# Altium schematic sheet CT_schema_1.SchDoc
size 532 x 258 mm
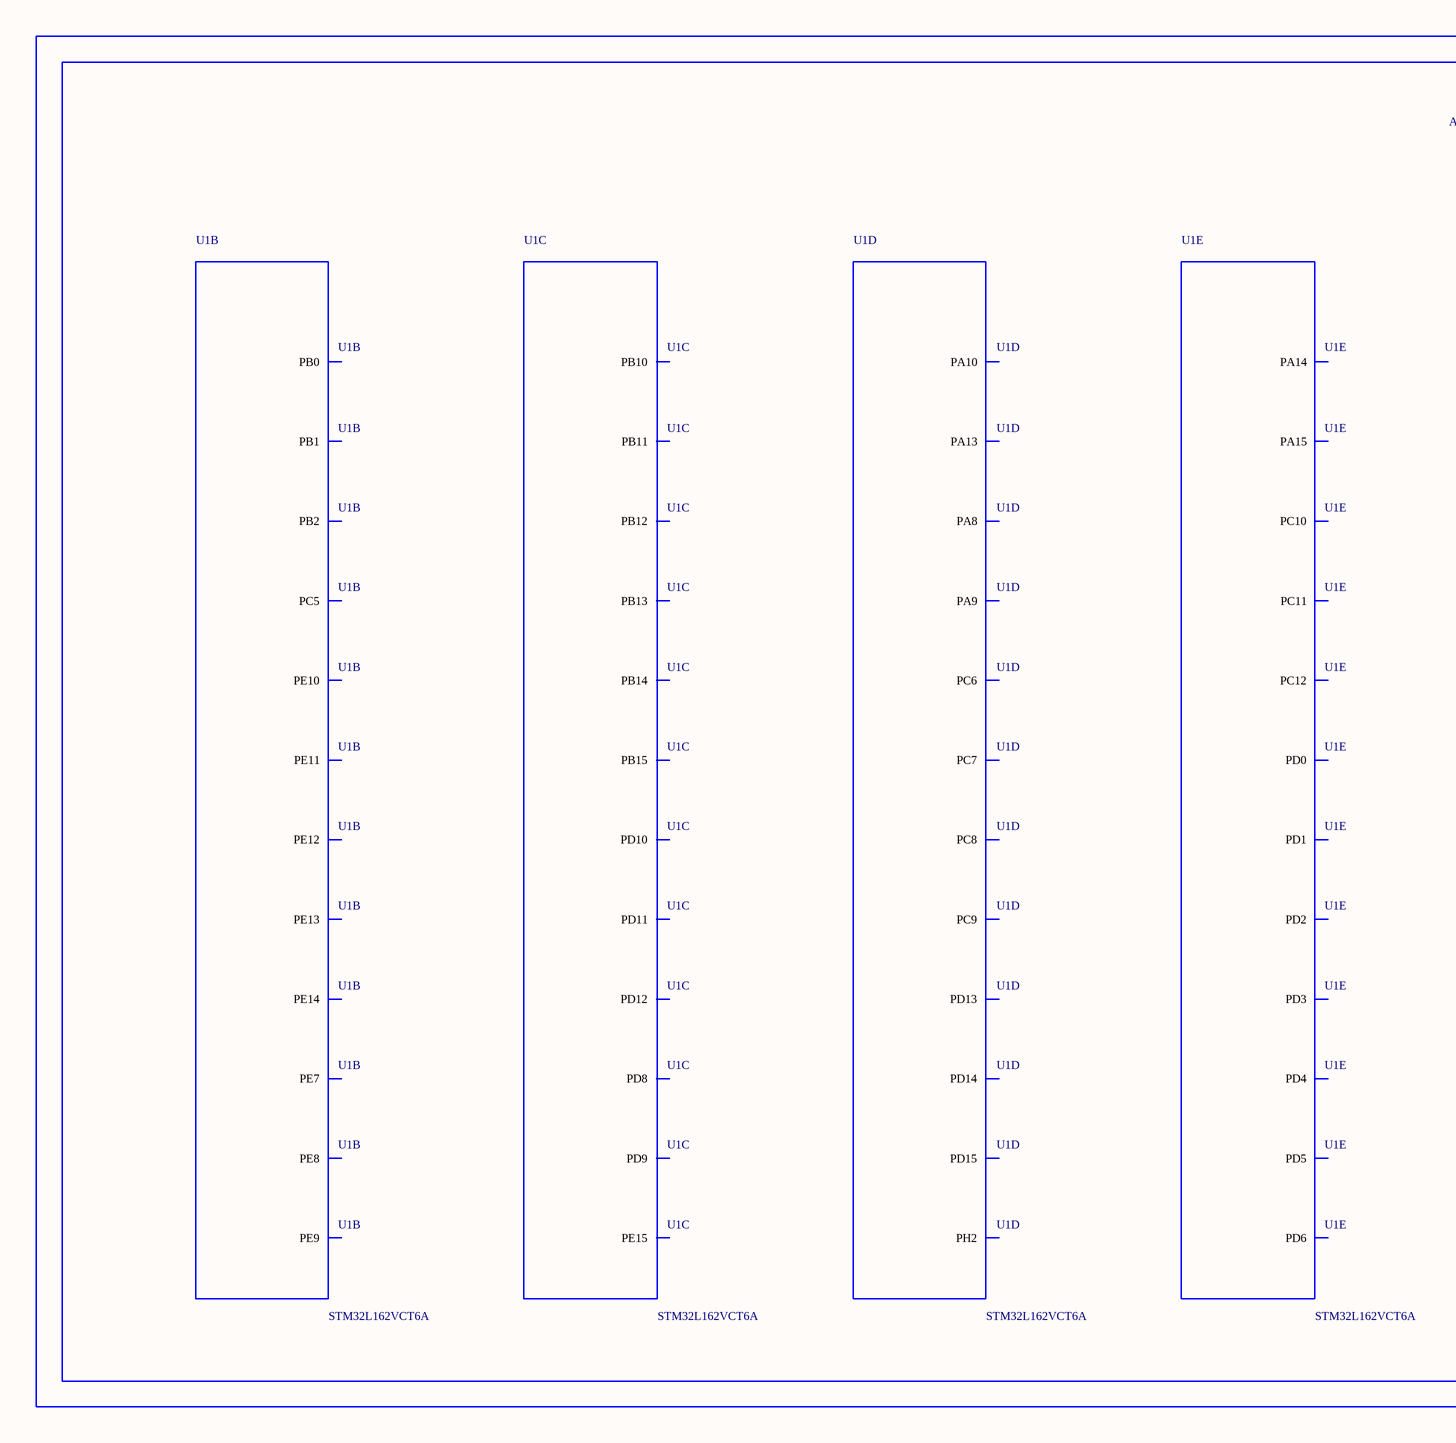
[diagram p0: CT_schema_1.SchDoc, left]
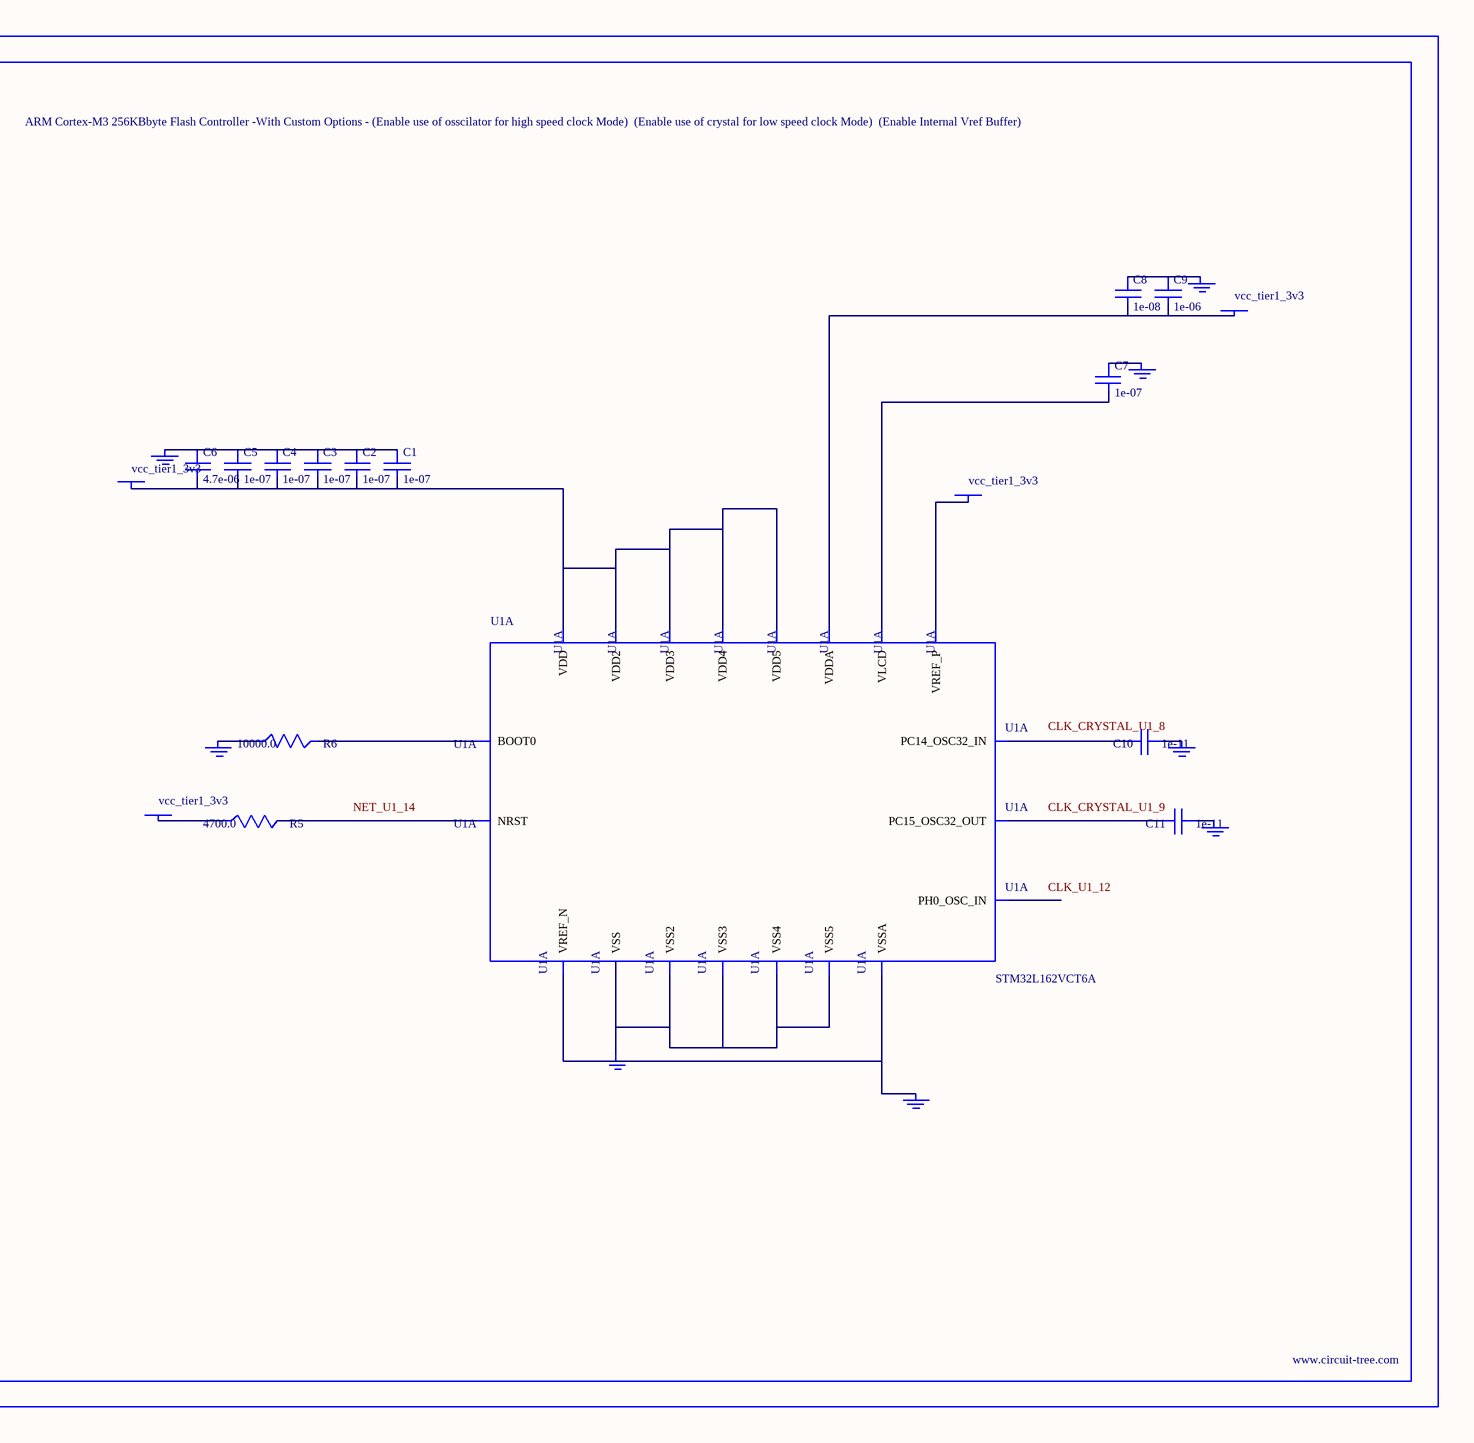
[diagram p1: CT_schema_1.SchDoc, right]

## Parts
BORDER0  (no value)
C1  1e-07  [C0603]
C2  1e-07  [C0603]
C3  1e-07  [C0603]
C4  1e-07  [C0603]
C5  1e-07  [C0603]
C6  4.7e-06  [C0603]
C7  1e-07  [C0603]
C8  1e-08  [C0603]
C9  1e-06  [C0603]
C10  1e-11  [C0402]
C11  1e-11  [C0402]
GND_INSTANCE_0_0  (no value)
GND_INSTANCE_0_1  (no value)
GND_INSTANCE_0_2  (no value)
GND_INSTANCE_0_3  (no value)
GND_INSTANCE_0_4  (no value)
GND_INSTANCE_0_5  (no value)
GND_INSTANCE_0_6  (no value)
GND_INSTANCE_0_7  (no value)
POWER_INSTANCE_0_0  vcc_tier1_3v3
POWER_INSTANCE_0_1  vcc_tier1_3v3
POWER_INSTANCE_0_2  vcc_tier1_3v3
POWER_INSTANCE_0_3  vcc_tier1_3v3
R5  4700.0  [R0603]
R6  10000.0  [R0603]
U1  STM32L162VCT6A  [LQFP100]  (parts A,B,C,D,E of 9)

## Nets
NetC1_1: C1.1 C2.1 C3.1 C4.1 C5.1 C6.1 GND_INSTANCE_0_3.0(GND)
NetC1_2: C1.2 C2.2 C3.2 C4.2 C5.2 C6.2 POWER_INSTANCE_0_0.0(PWR) U1.11(VDD) U1.28(VDD2) U1.50(VDD3) U1.75(VDD4) U1.100(VDD5)
NetC7_1: C7.1 GND_INSTANCE_0_0.0(GND)
NetC7_2: C7.2 U1.6(VLCD)
NetC8_1: C8.1 C9.1 GND_INSTANCE_0_5.0(GND)
NetC8_2: C8.2 C9.2 POWER_INSTANCE_0_2.0(PWR) U1.22(VDDA)
NetC10_1: C10.1 GND_INSTANCE_0_1.0(GND)
NetC10_2: C10.2 U1.8(PC14_OSC32_IN)
NetC11_1: C11.1 GND_INSTANCE_0_2.0(GND)
NetC11_2: C11.2 U1.9(PC15_OSC32_OUT)
NetGND_INSTANCE_0_4_0: GND_INSTANCE_0_4.0(GND) U1.19(VSSA) U1.20(VREF_N)
NetGND_INSTANCE_0_6_0: GND_INSTANCE_0_6.0(GND) R6.1
NetGND_INSTANCE_0_7_0: GND_INSTANCE_0_7.0(GND) U1.10(VSS) U1.27(VSS2) U1.49(VSS3) U1.74(VSS4) U1.99(VSS5)
NetPOWER_INSTANCE_0_1_0: POWER_INSTANCE_0_1.0(PWR) U1.21(VREF_P)
NetPOWER_INSTANCE_0_3_0: POWER_INSTANCE_0_3.0(PWR) R5.1
NetR5_2: R5.2 U1.14(NRST)
NetR6_2: R6.2 U1.94(BOOT0)

Not connected (* = marked no-connect by the designer): U1 12(PH0_OSC_IN) 34(PC5) 35(PB0) 36(PB1) 37(PB2) 38(PE7) 39(PE8) 40(PE9) 41(PE10) 42(PE11) 43(PE12) 44(PE13) 45(PE14) 46(PE15) 47(PB10) 48(PB11) 51(PB12) 52(PB13) 53(PB14) 54(PB15) 55(PD8) 56(PD9) 57(PD10) 58(PD11) 59(PD12) 60(PD13) 61(PD14) 62(PD15) 63(PC6) 64(PC7) 65(PC8) 66(PC9) 67(PA8) 68(PA9) 69(PA10) 72(PA13) 73(PH2) 76(PA14) 77(PA15) 78(PC10) 79(PC11) 80(PC12) 81(PD0) 82(PD1) 83(PD2) 84(PD3) 85(PD4) 86(PD5) 87(PD6)

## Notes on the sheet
- Labels drawn without touching a wire or pin: CLK_CRYSTAL_U1_8, CLK_CRYSTAL_U1_9, CLK_U1_12, NET_U1_14

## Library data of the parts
BORDER0 = BORDER_PAGE0
C1-C5 C7 = 06035C104K4Z2A
C6 = GRM188R6YA475KE15D
C8 = 06035C103K4Z2A
C9 = C0603C105K3RACTU
C10 C11 = C0402C100K3GACTU
GND_INSTANCE_0_0-GND_INSTANCE_0_7 = GND
POWER_INSTANCE_0_0-POWER_INSTANCE_0_3 = PWR
R5 = RC0603JR-074K7L
R6 = RC0603JR-0710KL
